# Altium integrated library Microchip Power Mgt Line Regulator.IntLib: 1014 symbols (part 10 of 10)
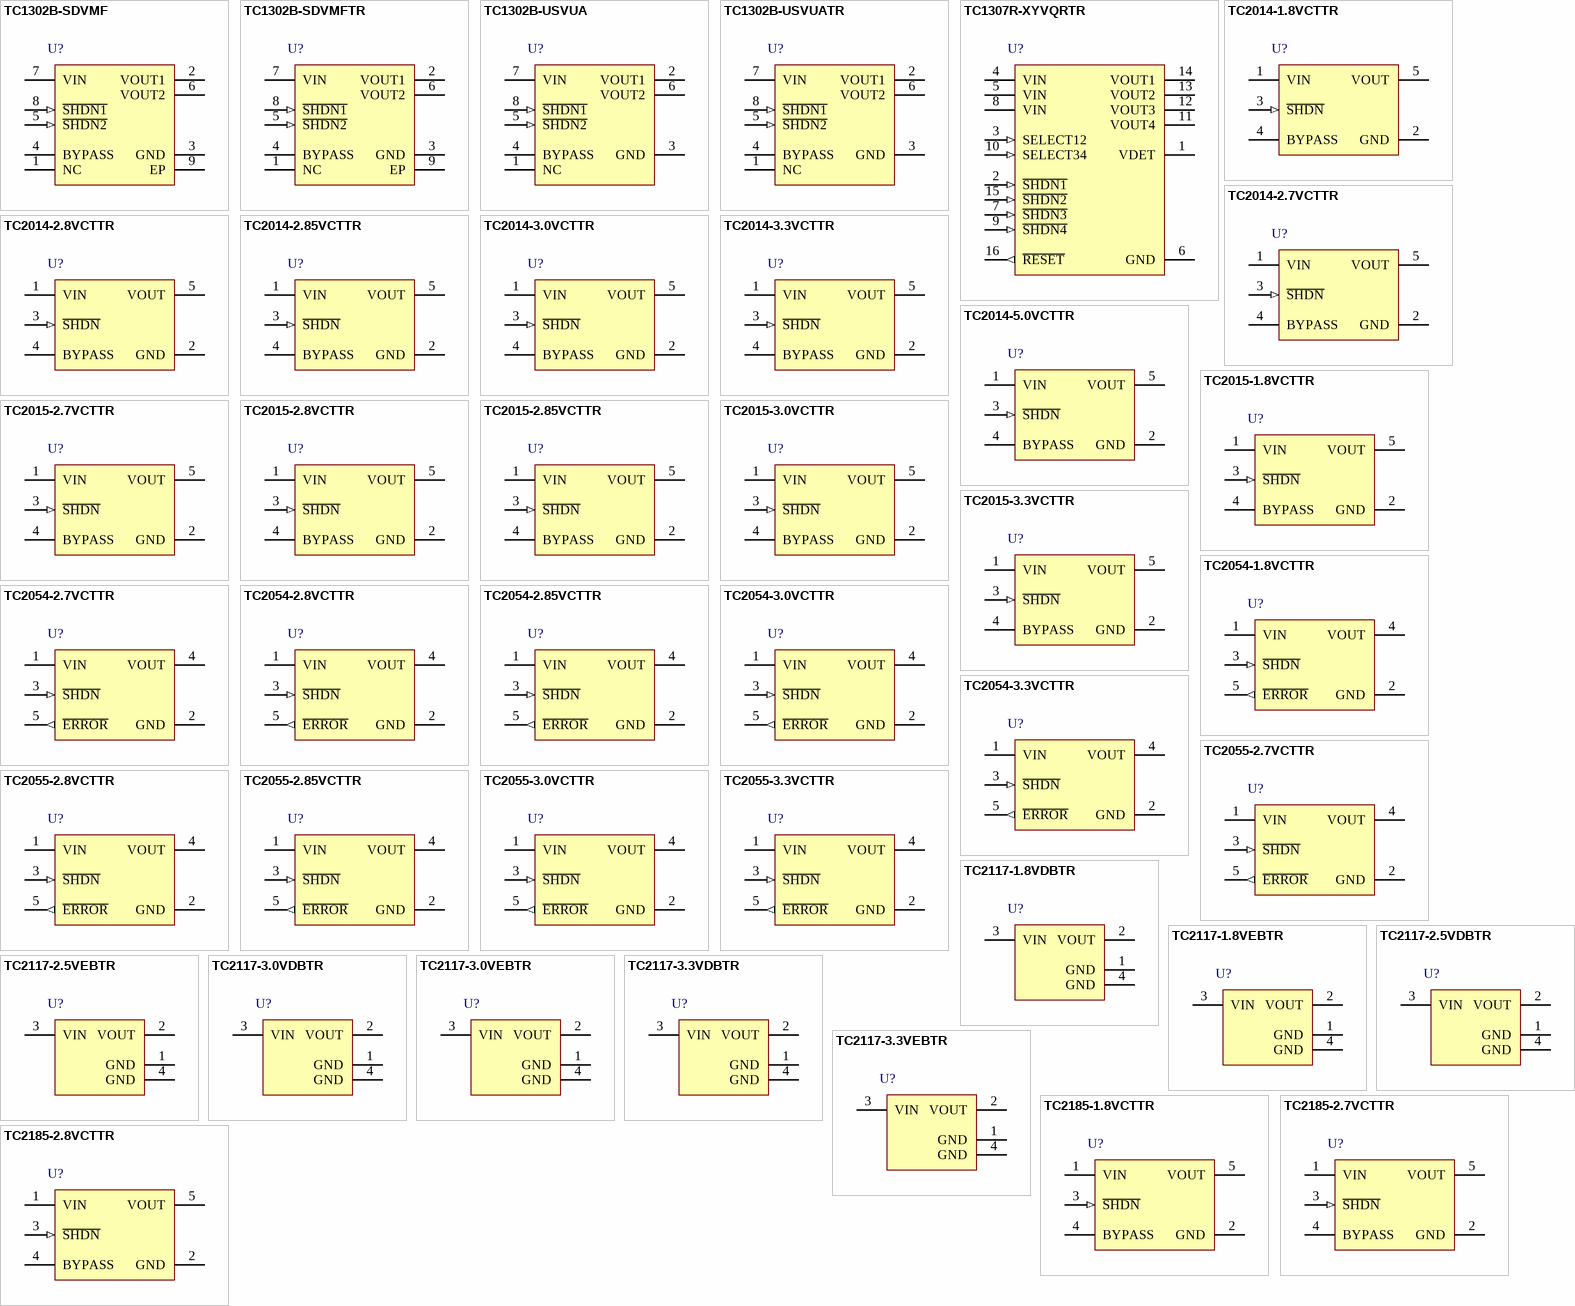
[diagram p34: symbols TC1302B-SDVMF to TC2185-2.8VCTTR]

## TC1302B-SDVMF
designator U?
Low Quiescent Current Dual Output LDO, 8-Pin DFN, Extended Temperature
footprint DFN-MF8 (SON, 8-Leads, Body 3x3mm, Pitch 0.65mm, Microchip Recommended)
pins: 1 NC, 2 VOUT1 (power), 3 GND (power), 4 BYPASS, 5 ~{SHDN2} (in), 6 VOUT2 (power), 7 VIN (power), 8 ~{SHDN1} (in), 9 EP (power)

## TC1302B-SDVMFTR
designator U?
Low Quiescent Current Dual Output LDO, 8-Pin DFN, Extended Temperature, Tape and Reel
footprint DFN-MF8 (SON, 8-Leads, Body 3x3mm, Pitch 0.65mm, Microchip Recommended)
pins: 1 NC, 2 VOUT1 (power), 3 GND (power), 4 BYPASS, 5 ~{SHDN2} (in), 6 VOUT2 (power), 7 VIN (power), 8 ~{SHDN1} (in), 9 EP (power)

## TC1302B-USVUA
designator U?
Low Quiescent Current Dual Output LDO, 8-Pin MSOP, Extended Temperature
footprint MSOP-UA8_N (TSOP, 8-Leads, Body 3x3mm, Pitch 0.65mm, IPC Medium Density)
footprint MSOP-UA8_L (TSOP, 8-Leads, Body 3x3mm, Pitch 0.65mm, IPC High Density)
footprint MSOP-UA8_M (TSOP, 8-Leads, Body 3x3mm, Pitch 0.65mm, IPC Low Density)
pins: 1 NC, 2 VOUT1 (power), 3 GND (power), 4 BYPASS, 5 ~{SHDN2} (in), 6 VOUT2 (power), 7 VIN (power), 8 ~{SHDN1} (in)

## TC1302B-USVUATR
designator U?
Low Quiescent Current Dual Output LDO, 8-Pin MSOP, Extended Temperature, Tape and Reel
footprint MSOP-UA8_N (TSOP, 8-Leads, Body 3x3mm, Pitch 0.65mm, IPC Medium Density)
footprint MSOP-UA8_L (TSOP, 8-Leads, Body 3x3mm, Pitch 0.65mm, IPC High Density)
footprint MSOP-UA8_M (TSOP, 8-Leads, Body 3x3mm, Pitch 0.65mm, IPC Low Density)
pins: 1 NC, 2 VOUT1 (power), 3 GND (power), 4 BYPASS, 5 ~{SHDN2} (in), 6 VOUT2 (power), 7 VIN (power), 8 ~{SHDN1} (in)

## TC1307R-XYVQRTR
designator U?
Four-Channel CMOS LDO with Select Mode, Shutdown and Independent Reset, 16-Pin QSOP, Extended Temperature, Tape and Reel
footprint QSOP-QR16_N (SOP, 16-Leads, Body 4.9x3.9mm, Pitch 0.635mm, IPC Medium Density)
footprint QSOP-QR16_L (SOP, 16-Leads, Body 4.9x3.9mm, Pitch 0.635mm, IPC High Density)
footprint QSOP-QR16_M (SOP, 16-Leads, Body 4.9x3.9mm, Pitch 0.635mm, IPC Low Density)
pins: 1 VDET (power), 2 ~{SHDN1} (in), 3 SELECT12 (in), 4 VIN (power), 5 VIN (power), 6 GND (power), 7 ~{SHDN3} (in), 8 VIN (power), 9 ~{SHDN4} (in), 10 SELECT34 (in), 11 VOUT4 (power), 12 VOUT3 (power), 13 VOUT2 (power), 14 VOUT1 (power), 15 ~{SHDN2} (in), 16 ~{RESET} (out)

## TC2014-1.8VCTTR
designator U?
50 mA, 100 mA, 150 mA CMOS LDOs with Shutdown and Reference Bypass, 5-Pin SOT-23, Extended Temperature, Tape and Reel
footprint SOT-23-CT5_N (SOT23, 5-Leads, Body 2.9x1.6mm, Pitch 0.95mm, Lead Span 2.7mm, IPC Medium Density)
footprint SOT-23-CT5_L (SOT23, 5-Leads, Body 2.9x1.6mm, Pitch 0.95mm, Lead Span 2.7mm, IPC High Density)
footprint SOT-23-CT5_M (SOT23, 5-Leads, Body 2.9x1.6mm, Pitch 0.95mm, Lead Span 2.7mm, IPC Low Density)
pins: 1 VIN (power), 2 GND (power), 3 ~{SHDN} (in), 4 BYPASS, 5 VOUT (power)

## TC2014-2.7VCTTR
designator U?
50 mA, 100 mA, 150 mA CMOS LDOs with Shutdown and Reference Bypass, 5-Pin SOT-23, Extended Temperature, Tape and Reel
footprint SOT-23-CT5_N (SOT23, 5-Leads, Body 2.9x1.6mm, Pitch 0.95mm, Lead Span 2.7mm, IPC Medium Density)
footprint SOT-23-CT5_L (SOT23, 5-Leads, Body 2.9x1.6mm, Pitch 0.95mm, Lead Span 2.7mm, IPC High Density)
footprint SOT-23-CT5_M (SOT23, 5-Leads, Body 2.9x1.6mm, Pitch 0.95mm, Lead Span 2.7mm, IPC Low Density)
pins: 1 VIN (power), 2 GND (power), 3 ~{SHDN} (in), 4 BYPASS, 5 VOUT (power)

## TC2014-2.8VCTTR
designator U?
50 mA, 100 mA, 150 mA CMOS LDOs with Shutdown and Reference Bypass, 5-Pin SOT-23, Extended Temperature, Tape and Reel
footprint SOT-23-CT5_N (SOT23, 5-Leads, Body 2.9x1.6mm, Pitch 0.95mm, Lead Span 2.7mm, IPC Medium Density)
footprint SOT-23-CT5_L (SOT23, 5-Leads, Body 2.9x1.6mm, Pitch 0.95mm, Lead Span 2.7mm, IPC High Density)
footprint SOT-23-CT5_M (SOT23, 5-Leads, Body 2.9x1.6mm, Pitch 0.95mm, Lead Span 2.7mm, IPC Low Density)
pins: 1 VIN (power), 2 GND (power), 3 ~{SHDN} (in), 4 BYPASS, 5 VOUT (power)

## TC2014-2.85VCTTR
designator U?
50 mA, 100 mA, 150 mA CMOS LDOs with Shutdown and Reference Bypass, 5-Pin SOT-23, Extended Temperature, Tape and Reel
footprint SOT-23-CT5_N (SOT23, 5-Leads, Body 2.9x1.6mm, Pitch 0.95mm, Lead Span 2.7mm, IPC Medium Density)
footprint SOT-23-CT5_L (SOT23, 5-Leads, Body 2.9x1.6mm, Pitch 0.95mm, Lead Span 2.7mm, IPC High Density)
footprint SOT-23-CT5_M (SOT23, 5-Leads, Body 2.9x1.6mm, Pitch 0.95mm, Lead Span 2.7mm, IPC Low Density)
pins: 1 VIN (power), 2 GND (power), 3 ~{SHDN} (in), 4 BYPASS, 5 VOUT (power)

## TC2014-3.0VCTTR
designator U?
50 mA, 100 mA, 150 mA CMOS LDOs with Shutdown and Reference Bypass, 5-Pin SOT-23, Extended Temperature, Tape and Reel
footprint SOT-23-CT5_N (SOT23, 5-Leads, Body 2.9x1.6mm, Pitch 0.95mm, Lead Span 2.7mm, IPC Medium Density)
footprint SOT-23-CT5_L (SOT23, 5-Leads, Body 2.9x1.6mm, Pitch 0.95mm, Lead Span 2.7mm, IPC High Density)
footprint SOT-23-CT5_M (SOT23, 5-Leads, Body 2.9x1.6mm, Pitch 0.95mm, Lead Span 2.7mm, IPC Low Density)
pins: 1 VIN (power), 2 GND (power), 3 ~{SHDN} (in), 4 BYPASS, 5 VOUT (power)

## TC2014-3.3VCTTR
designator U?
50 mA, 100 mA, 150 mA CMOS LDOs with Shutdown and Reference Bypass, 5-Pin SOT-23, Extended Temperature, Tape and Reel
footprint SOT-23-CT5_N (SOT23, 5-Leads, Body 2.9x1.6mm, Pitch 0.95mm, Lead Span 2.7mm, IPC Medium Density)
footprint SOT-23-CT5_L (SOT23, 5-Leads, Body 2.9x1.6mm, Pitch 0.95mm, Lead Span 2.7mm, IPC High Density)
footprint SOT-23-CT5_M (SOT23, 5-Leads, Body 2.9x1.6mm, Pitch 0.95mm, Lead Span 2.7mm, IPC Low Density)
pins: 1 VIN (power), 2 GND (power), 3 ~{SHDN} (in), 4 BYPASS, 5 VOUT (power)

## TC2014-5.0VCTTR
designator U?
50 mA, 100 mA, 150 mA CMOS LDOs with Shutdown and Reference Bypass, 5-Pin SOT-23, Extended Temperature, Tape and Reel
footprint SOT-23-CT5_N (SOT23, 5-Leads, Body 2.9x1.6mm, Pitch 0.95mm, Lead Span 2.7mm, IPC Medium Density)
footprint SOT-23-CT5_L (SOT23, 5-Leads, Body 2.9x1.6mm, Pitch 0.95mm, Lead Span 2.7mm, IPC High Density)
footprint SOT-23-CT5_M (SOT23, 5-Leads, Body 2.9x1.6mm, Pitch 0.95mm, Lead Span 2.7mm, IPC Low Density)
pins: 1 VIN (power), 2 GND (power), 3 ~{SHDN} (in), 4 BYPASS, 5 VOUT (power)

## TC2015-1.8VCTTR
designator U?
50 mA, 100 mA, 150 mA CMOS LDOs with Shutdown and Reference Bypass, 5-Pin SOT-23, Extended Temperature, Tape and Reel
footprint SOT-23-CT5_N (SOT23, 5-Leads, Body 2.9x1.6mm, Pitch 0.95mm, Lead Span 2.7mm, IPC Medium Density)
footprint SOT-23-CT5_L (SOT23, 5-Leads, Body 2.9x1.6mm, Pitch 0.95mm, Lead Span 2.7mm, IPC High Density)
footprint SOT-23-CT5_M (SOT23, 5-Leads, Body 2.9x1.6mm, Pitch 0.95mm, Lead Span 2.7mm, IPC Low Density)
pins: 1 VIN (power), 2 GND (power), 3 ~{SHDN} (in), 4 BYPASS, 5 VOUT (power)

## TC2015-2.7VCTTR
designator U?
50 mA, 100 mA, 150 mA CMOS LDOs with Shutdown and Reference Bypass, 5-Pin SOT-23, Extended Temperature, Tape and Reel
footprint SOT-23-CT5_N (SOT23, 5-Leads, Body 2.9x1.6mm, Pitch 0.95mm, Lead Span 2.7mm, IPC Medium Density)
footprint SOT-23-CT5_L (SOT23, 5-Leads, Body 2.9x1.6mm, Pitch 0.95mm, Lead Span 2.7mm, IPC High Density)
footprint SOT-23-CT5_M (SOT23, 5-Leads, Body 2.9x1.6mm, Pitch 0.95mm, Lead Span 2.7mm, IPC Low Density)
pins: 1 VIN (power), 2 GND (power), 3 ~{SHDN} (in), 4 BYPASS, 5 VOUT (power)

## TC2015-2.8VCTTR
designator U?
50 mA, 100 mA, 150 mA CMOS LDOs with Shutdown and Reference Bypass, 5-Pin SOT-23, Extended Temperature, Tape and Reel
footprint SOT-23-CT5_N (SOT23, 5-Leads, Body 2.9x1.6mm, Pitch 0.95mm, Lead Span 2.7mm, IPC Medium Density)
footprint SOT-23-CT5_L (SOT23, 5-Leads, Body 2.9x1.6mm, Pitch 0.95mm, Lead Span 2.7mm, IPC High Density)
footprint SOT-23-CT5_M (SOT23, 5-Leads, Body 2.9x1.6mm, Pitch 0.95mm, Lead Span 2.7mm, IPC Low Density)
pins: 1 VIN (power), 2 GND (power), 3 ~{SHDN} (in), 4 BYPASS, 5 VOUT (power)

## TC2015-2.85VCTTR
designator U?
50 mA, 100 mA, 150 mA CMOS LDOs with Shutdown and Reference Bypass, 5-Pin SOT-23, Extended Temperature, Tape and Reel
footprint SOT-23-CT5_N (SOT23, 5-Leads, Body 2.9x1.6mm, Pitch 0.95mm, Lead Span 2.7mm, IPC Medium Density)
footprint SOT-23-CT5_L (SOT23, 5-Leads, Body 2.9x1.6mm, Pitch 0.95mm, Lead Span 2.7mm, IPC High Density)
footprint SOT-23-CT5_M (SOT23, 5-Leads, Body 2.9x1.6mm, Pitch 0.95mm, Lead Span 2.7mm, IPC Low Density)
pins: 1 VIN (power), 2 GND (power), 3 ~{SHDN} (in), 4 BYPASS, 5 VOUT (power)

## TC2015-3.0VCTTR
designator U?
50 mA, 100 mA, 150 mA CMOS LDOs with Shutdown and Reference Bypass, 5-Pin SOT-23, Extended Temperature, Tape and Reel
footprint SOT-23-CT5_N (SOT23, 5-Leads, Body 2.9x1.6mm, Pitch 0.95mm, Lead Span 2.7mm, IPC Medium Density)
footprint SOT-23-CT5_L (SOT23, 5-Leads, Body 2.9x1.6mm, Pitch 0.95mm, Lead Span 2.7mm, IPC High Density)
footprint SOT-23-CT5_M (SOT23, 5-Leads, Body 2.9x1.6mm, Pitch 0.95mm, Lead Span 2.7mm, IPC Low Density)
pins: 1 VIN (power), 2 GND (power), 3 ~{SHDN} (in), 4 BYPASS, 5 VOUT (power)

## TC2015-3.3VCTTR
designator U?
50 mA, 100 mA, 150 mA CMOS LDOs with Shutdown and Reference Bypass, 5-Pin SOT-23, Extended Temperature, Tape and Reel
footprint SOT-23-CT5_N (SOT23, 5-Leads, Body 2.9x1.6mm, Pitch 0.95mm, Lead Span 2.7mm, IPC Medium Density)
footprint SOT-23-CT5_L (SOT23, 5-Leads, Body 2.9x1.6mm, Pitch 0.95mm, Lead Span 2.7mm, IPC High Density)
footprint SOT-23-CT5_M (SOT23, 5-Leads, Body 2.9x1.6mm, Pitch 0.95mm, Lead Span 2.7mm, IPC Low Density)
pins: 1 VIN (power), 2 GND (power), 3 ~{SHDN} (in), 4 BYPASS, 5 VOUT (power)

## TC2054-1.8VCTTR
designator U?
50 mA, 100 mA, and 150 mA CMOS LDOs with Shutdown and Active-Low Error Output, 5-Pin SOT-23, Extended Temperature, Tape and Reel
footprint SOT-23-CT5_N (SOT23, 5-Leads, Body 2.9x1.6mm, Pitch 0.95mm, Lead Span 2.7mm, IPC Medium Density)
footprint SOT-23-CT5_L (SOT23, 5-Leads, Body 2.9x1.6mm, Pitch 0.95mm, Lead Span 2.7mm, IPC High Density)
footprint SOT-23-CT5_M (SOT23, 5-Leads, Body 2.9x1.6mm, Pitch 0.95mm, Lead Span 2.7mm, IPC Low Density)
pins: 1 VIN (power), 2 GND (power), 3 ~{SHDN} (in), 4 VOUT (power), 5 ~{ERROR} (out)

## TC2054-2.7VCTTR
designator U?
50 mA, 100 mA, and 150 mA CMOS LDOs with Shutdown and Active-Low Error Output, 5-Pin SOT-23, Extended Temperature, Tape and Reel
footprint SOT-23-CT5_N (SOT23, 5-Leads, Body 2.9x1.6mm, Pitch 0.95mm, Lead Span 2.7mm, IPC Medium Density)
footprint SOT-23-CT5_L (SOT23, 5-Leads, Body 2.9x1.6mm, Pitch 0.95mm, Lead Span 2.7mm, IPC High Density)
footprint SOT-23-CT5_M (SOT23, 5-Leads, Body 2.9x1.6mm, Pitch 0.95mm, Lead Span 2.7mm, IPC Low Density)
pins: 1 VIN (power), 2 GND (power), 3 ~{SHDN} (in), 4 VOUT (power), 5 ~{ERROR} (out)

## TC2054-2.8VCTTR
designator U?
50 mA, 100 mA, and 150 mA CMOS LDOs with Shutdown and Active-Low Error Output, 5-Pin SOT-23, Extended Temperature, Tape and Reel
footprint SOT-23-CT5_N (SOT23, 5-Leads, Body 2.9x1.6mm, Pitch 0.95mm, Lead Span 2.7mm, IPC Medium Density)
footprint SOT-23-CT5_L (SOT23, 5-Leads, Body 2.9x1.6mm, Pitch 0.95mm, Lead Span 2.7mm, IPC High Density)
footprint SOT-23-CT5_M (SOT23, 5-Leads, Body 2.9x1.6mm, Pitch 0.95mm, Lead Span 2.7mm, IPC Low Density)
pins: 1 VIN (power), 2 GND (power), 3 ~{SHDN} (in), 4 VOUT (power), 5 ~{ERROR} (out)

## TC2054-2.85VCTTR
designator U?
50 mA, 100 mA, and 150 mA CMOS LDOs with Shutdown and Active-Low Error Output, 5-Pin SOT-23, Extended Temperature, Tape and Reel
footprint SOT-23-CT5_N (SOT23, 5-Leads, Body 2.9x1.6mm, Pitch 0.95mm, Lead Span 2.7mm, IPC Medium Density)
footprint SOT-23-CT5_L (SOT23, 5-Leads, Body 2.9x1.6mm, Pitch 0.95mm, Lead Span 2.7mm, IPC High Density)
footprint SOT-23-CT5_M (SOT23, 5-Leads, Body 2.9x1.6mm, Pitch 0.95mm, Lead Span 2.7mm, IPC Low Density)
pins: 1 VIN (power), 2 GND (power), 3 ~{SHDN} (in), 4 VOUT (power), 5 ~{ERROR} (out)

## TC2054-3.0VCTTR
designator U?
50 mA, 100 mA, and 150 mA CMOS LDOs with Shutdown and Active-Low Error Output, 5-Pin SOT-23, Extended Temperature, Tape and Reel
footprint SOT-23-CT5_N (SOT23, 5-Leads, Body 2.9x1.6mm, Pitch 0.95mm, Lead Span 2.7mm, IPC Medium Density)
footprint SOT-23-CT5_L (SOT23, 5-Leads, Body 2.9x1.6mm, Pitch 0.95mm, Lead Span 2.7mm, IPC High Density)
footprint SOT-23-CT5_M (SOT23, 5-Leads, Body 2.9x1.6mm, Pitch 0.95mm, Lead Span 2.7mm, IPC Low Density)
pins: 1 VIN (power), 2 GND (power), 3 ~{SHDN} (in), 4 VOUT (power), 5 ~{ERROR} (out)

## TC2054-3.3VCTTR
designator U?
50 mA, 100 mA, and 150 mA CMOS LDOs with Shutdown and Active-Low Error Output, 5-Pin SOT-23, Extended Temperature, Tape and Reel
footprint SOT-23-CT5_N (SOT23, 5-Leads, Body 2.9x1.6mm, Pitch 0.95mm, Lead Span 2.7mm, IPC Medium Density)
footprint SOT-23-CT5_L (SOT23, 5-Leads, Body 2.9x1.6mm, Pitch 0.95mm, Lead Span 2.7mm, IPC High Density)
footprint SOT-23-CT5_M (SOT23, 5-Leads, Body 2.9x1.6mm, Pitch 0.95mm, Lead Span 2.7mm, IPC Low Density)
pins: 1 VIN (power), 2 GND (power), 3 ~{SHDN} (in), 4 VOUT (power), 5 ~{ERROR} (out)

## TC2055-2.7VCTTR
designator U?
50 mA, 100 mA, and 150 mA CMOS LDOs with Shutdown and Active-Low Error Output, 5-Pin SOT-23, Extended Temperature, Tape and Reel
footprint SOT-23-CT5_N (SOT23, 5-Leads, Body 2.9x1.6mm, Pitch 0.95mm, Lead Span 2.7mm, IPC Medium Density)
footprint SOT-23-CT5_L (SOT23, 5-Leads, Body 2.9x1.6mm, Pitch 0.95mm, Lead Span 2.7mm, IPC High Density)
footprint SOT-23-CT5_M (SOT23, 5-Leads, Body 2.9x1.6mm, Pitch 0.95mm, Lead Span 2.7mm, IPC Low Density)
pins: 1 VIN (power), 2 GND (power), 3 ~{SHDN} (in), 4 VOUT (power), 5 ~{ERROR} (out)

## TC2055-2.8VCTTR
designator U?
50 mA, 100 mA, and 150 mA CMOS LDOs with Shutdown and Active-Low Error Output, 5-Pin SOT-23, Extended Temperature, Tape and Reel
footprint SOT-23-CT5_N (SOT23, 5-Leads, Body 2.9x1.6mm, Pitch 0.95mm, Lead Span 2.7mm, IPC Medium Density)
footprint SOT-23-CT5_L (SOT23, 5-Leads, Body 2.9x1.6mm, Pitch 0.95mm, Lead Span 2.7mm, IPC High Density)
footprint SOT-23-CT5_M (SOT23, 5-Leads, Body 2.9x1.6mm, Pitch 0.95mm, Lead Span 2.7mm, IPC Low Density)
pins: 1 VIN (power), 2 GND (power), 3 ~{SHDN} (in), 4 VOUT (power), 5 ~{ERROR} (out)

## TC2055-2.85VCTTR
designator U?
50 mA, 100 mA, and 150 mA CMOS LDOs with Shutdown and Active-Low Error Output, 5-Pin SOT-23, Extended Temperature, Tape and Reel
footprint SOT-23-CT5_N (SOT23, 5-Leads, Body 2.9x1.6mm, Pitch 0.95mm, Lead Span 2.7mm, IPC Medium Density)
footprint SOT-23-CT5_L (SOT23, 5-Leads, Body 2.9x1.6mm, Pitch 0.95mm, Lead Span 2.7mm, IPC High Density)
footprint SOT-23-CT5_M (SOT23, 5-Leads, Body 2.9x1.6mm, Pitch 0.95mm, Lead Span 2.7mm, IPC Low Density)
pins: 1 VIN (power), 2 GND (power), 3 ~{SHDN} (in), 4 VOUT (power), 5 ~{ERROR} (out)

## TC2055-3.0VCTTR
designator U?
50 mA, 100 mA, and 150 mA CMOS LDOs with Shutdown and Active-Low Error Output, 5-Pin SOT-23, Extended Temperature, Tape and Reel
footprint SOT-23-CT5_N (SOT23, 5-Leads, Body 2.9x1.6mm, Pitch 0.95mm, Lead Span 2.7mm, IPC Medium Density)
footprint SOT-23-CT5_L (SOT23, 5-Leads, Body 2.9x1.6mm, Pitch 0.95mm, Lead Span 2.7mm, IPC High Density)
footprint SOT-23-CT5_M (SOT23, 5-Leads, Body 2.9x1.6mm, Pitch 0.95mm, Lead Span 2.7mm, IPC Low Density)
pins: 1 VIN (power), 2 GND (power), 3 ~{SHDN} (in), 4 VOUT (power), 5 ~{ERROR} (out)

## TC2055-3.3VCTTR
designator U?
50 mA, 100 mA, and 150 mA CMOS LDOs with Shutdown and Active-Low Error Output, 5-Pin SOT-23, Extended Temperature, Tape and Reel
footprint SOT-23-CT5_N (SOT23, 5-Leads, Body 2.9x1.6mm, Pitch 0.95mm, Lead Span 2.7mm, IPC Medium Density)
footprint SOT-23-CT5_L (SOT23, 5-Leads, Body 2.9x1.6mm, Pitch 0.95mm, Lead Span 2.7mm, IPC High Density)
footprint SOT-23-CT5_M (SOT23, 5-Leads, Body 2.9x1.6mm, Pitch 0.95mm, Lead Span 2.7mm, IPC Low Density)
pins: 1 VIN (power), 2 GND (power), 3 ~{SHDN} (in), 4 VOUT (power), 5 ~{ERROR} (out)

## TC2117-1.8VDBTR
designator U?
800 mA Fixed Low Dropout Positive Regulator, 3-Pin SOT-223, Extended Temperature, Tape and Reel
footprint SOT-223-DB3_N (SOT223, 4-Leads, Body 6.5x3.5mm, Pitch 2.3mm, Lead Span 7mm, IPC Medium Density)
footprint SOT-223-DB3_L (SOT223, 4-Leads, Body 6.5x3.5mm, Pitch 2.3mm, Lead Span 7mm, IPC High Density)
footprint SOT-223-DB3_M (SOT223, 4-Leads, Body 6.5x3.5mm, Pitch 2.3mm, Lead Span 7mm, IPC Low Density)
pins: 1 GND (power), 2 VOUT (power), 3 VIN (power), 4 GND (power)

## TC2117-1.8VEBTR
designator U?
800 mA Fixed Low Dropout Positive Regulator, 3-Pin DDPAK, Extended Temperature, Tape and Reel
footprint DDPAK-EB3_N (D2-PAK, 4-Leads, Body 9x10.2mm, Pitch 2.54mm, Lead Span 14.9mm, IPC Medium Density)
footprint DDPAK-EB3_L (D2-PAK, 4-Leads, Body 9x10.2mm, Pitch 2.54mm, Lead Span 14.9mm, IPC High Density)
footprint DDPAK-EB3_M (D2-PAK, 4-Leads, Body 9x10.2mm, Pitch 2.54mm, Lead Span 14.9mm, IPC Low Density)
pins: 1 GND (power), 2 VOUT (power), 3 VIN (power), 4 GND (power)

## TC2117-2.5VDBTR
designator U?
800 mA Fixed Low Dropout Positive Regulator, 3-Pin SOT-223, Extended Temperature, Tape and Reel
footprint SOT-223-DB3_N (SOT223, 4-Leads, Body 6.5x3.5mm, Pitch 2.3mm, Lead Span 7mm, IPC Medium Density)
footprint SOT-223-DB3_L (SOT223, 4-Leads, Body 6.5x3.5mm, Pitch 2.3mm, Lead Span 7mm, IPC High Density)
footprint SOT-223-DB3_M (SOT223, 4-Leads, Body 6.5x3.5mm, Pitch 2.3mm, Lead Span 7mm, IPC Low Density)
pins: 1 GND (power), 2 VOUT (power), 3 VIN (power), 4 GND (power)

## TC2117-2.5VEBTR
designator U?
800 mA Fixed Low Dropout Positive Regulator, 3-Pin DDPAK, Extended Temperature, Tape and Reel
footprint DDPAK-EB3_N (D2-PAK, 4-Leads, Body 9x10.2mm, Pitch 2.54mm, Lead Span 14.9mm, IPC Medium Density)
footprint DDPAK-EB3_L (D2-PAK, 4-Leads, Body 9x10.2mm, Pitch 2.54mm, Lead Span 14.9mm, IPC High Density)
footprint DDPAK-EB3_M (D2-PAK, 4-Leads, Body 9x10.2mm, Pitch 2.54mm, Lead Span 14.9mm, IPC Low Density)
pins: 1 GND (power), 2 VOUT (power), 3 VIN (power), 4 GND (power)

## TC2117-3.0VDBTR
designator U?
800 mA Fixed Low Dropout Positive Regulator, 3-Pin SOT-223, Extended Temperature, Tape and Reel
footprint SOT-223-DB3_N (SOT223, 4-Leads, Body 6.5x3.5mm, Pitch 2.3mm, Lead Span 7mm, IPC Medium Density)
footprint SOT-223-DB3_L (SOT223, 4-Leads, Body 6.5x3.5mm, Pitch 2.3mm, Lead Span 7mm, IPC High Density)
footprint SOT-223-DB3_M (SOT223, 4-Leads, Body 6.5x3.5mm, Pitch 2.3mm, Lead Span 7mm, IPC Low Density)
pins: 1 GND (power), 2 VOUT (power), 3 VIN (power), 4 GND (power)

## TC2117-3.0VEBTR
designator U?
800 mA Fixed Low Dropout Positive Regulator, 3-Pin DDPAK, Extended Temperature, Tape and Reel
footprint DDPAK-EB3_N (D2-PAK, 4-Leads, Body 9x10.2mm, Pitch 2.54mm, Lead Span 14.9mm, IPC Medium Density)
footprint DDPAK-EB3_L (D2-PAK, 4-Leads, Body 9x10.2mm, Pitch 2.54mm, Lead Span 14.9mm, IPC High Density)
footprint DDPAK-EB3_M (D2-PAK, 4-Leads, Body 9x10.2mm, Pitch 2.54mm, Lead Span 14.9mm, IPC Low Density)
pins: 1 GND (power), 2 VOUT (power), 3 VIN (power), 4 GND (power)

## TC2117-3.3VDBTR
designator U?
800 mA Fixed Low Dropout Positive Regulator, 3-Pin SOT-223, Extended Temperature, Tape and Reel
footprint SOT-223-DB3_N (SOT223, 4-Leads, Body 6.5x3.5mm, Pitch 2.3mm, Lead Span 7mm, IPC Medium Density)
footprint SOT-223-DB3_L (SOT223, 4-Leads, Body 6.5x3.5mm, Pitch 2.3mm, Lead Span 7mm, IPC High Density)
footprint SOT-223-DB3_M (SOT223, 4-Leads, Body 6.5x3.5mm, Pitch 2.3mm, Lead Span 7mm, IPC Low Density)
pins: 1 GND (power), 2 VOUT (power), 3 VIN (power), 4 GND (power)

## TC2117-3.3VEBTR
designator U?
800 mA Fixed Low Dropout Positive Regulator, 3-Pin DDPAK, Extended Temperature, Tape and Reel
footprint DDPAK-EB3_N (D2-PAK, 4-Leads, Body 9x10.2mm, Pitch 2.54mm, Lead Span 14.9mm, IPC Medium Density)
footprint DDPAK-EB3_L (D2-PAK, 4-Leads, Body 9x10.2mm, Pitch 2.54mm, Lead Span 14.9mm, IPC High Density)
footprint DDPAK-EB3_M (D2-PAK, 4-Leads, Body 9x10.2mm, Pitch 2.54mm, Lead Span 14.9mm, IPC Low Density)
pins: 1 GND (power), 2 VOUT (power), 3 VIN (power), 4 GND (power)

## TC2185-1.8VCTTR
designator U?
50 mA, 100 mA, 150 mA CMOS LDOs with Shutdown and Reference Bypass, 5-Pin SOT-23, Extended Temperature, Tape and Reel
footprint SOT-23-CT5_N (SOT23, 5-Leads, Body 2.9x1.6mm, Pitch 0.95mm, Lead Span 2.7mm, IPC Medium Density)
footprint SOT-23-CT5_L (SOT23, 5-Leads, Body 2.9x1.6mm, Pitch 0.95mm, Lead Span 2.7mm, IPC High Density)
footprint SOT-23-CT5_M (SOT23, 5-Leads, Body 2.9x1.6mm, Pitch 0.95mm, Lead Span 2.7mm, IPC Low Density)
pins: 1 VIN (power), 2 GND (power), 3 ~{SHDN} (in), 4 BYPASS, 5 VOUT (power)

## TC2185-2.7VCTTR
designator U?
50 mA, 100 mA, 150 mA CMOS LDOs with Shutdown and Reference Bypass, 5-Pin SOT-23, Extended Temperature, Tape and Reel
footprint SOT-23-CT5_N (SOT23, 5-Leads, Body 2.9x1.6mm, Pitch 0.95mm, Lead Span 2.7mm, IPC Medium Density)
footprint SOT-23-CT5_L (SOT23, 5-Leads, Body 2.9x1.6mm, Pitch 0.95mm, Lead Span 2.7mm, IPC High Density)
footprint SOT-23-CT5_M (SOT23, 5-Leads, Body 2.9x1.6mm, Pitch 0.95mm, Lead Span 2.7mm, IPC Low Density)
pins: 1 VIN (power), 2 GND (power), 3 ~{SHDN} (in), 4 BYPASS, 5 VOUT (power)

## TC2185-2.8VCTTR
designator U?
50 mA, 100 mA, 150 mA CMOS LDOs with Shutdown and Reference Bypass, 5-Pin SOT-23, Extended Temperature, Tape and Reel
footprint SOT-23-CT5_N (SOT23, 5-Leads, Body 2.9x1.6mm, Pitch 0.95mm, Lead Span 2.7mm, IPC Medium Density)
footprint SOT-23-CT5_L (SOT23, 5-Leads, Body 2.9x1.6mm, Pitch 0.95mm, Lead Span 2.7mm, IPC High Density)
footprint SOT-23-CT5_M (SOT23, 5-Leads, Body 2.9x1.6mm, Pitch 0.95mm, Lead Span 2.7mm, IPC Low Density)
pins: 1 VIN (power), 2 GND (power), 3 ~{SHDN} (in), 4 BYPASS, 5 VOUT (power)

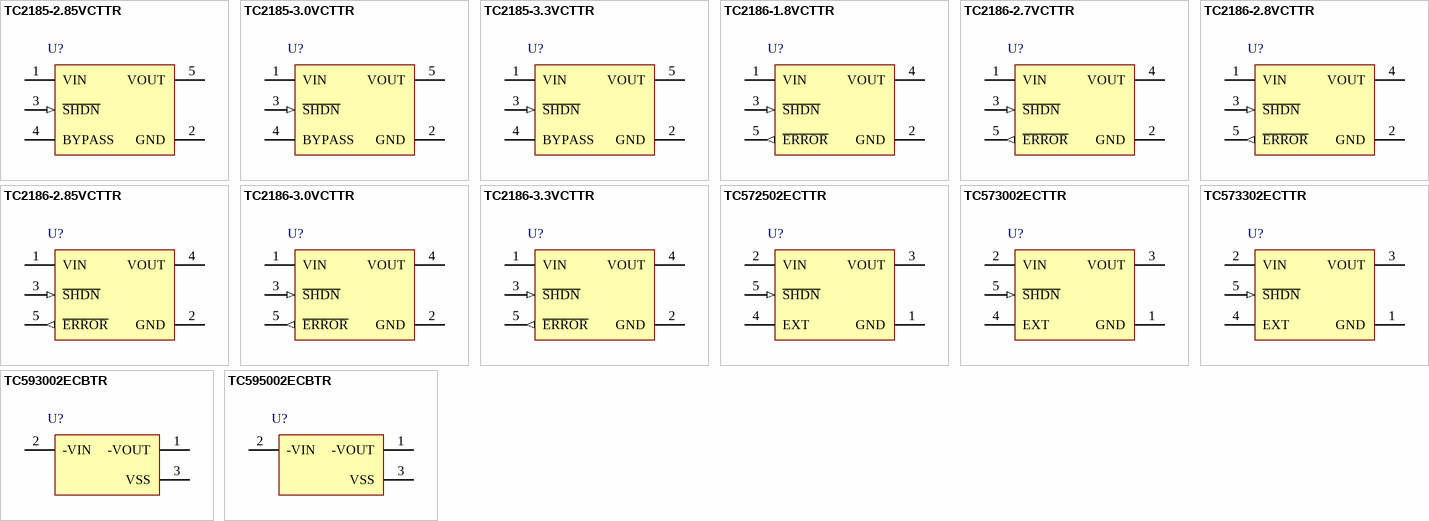
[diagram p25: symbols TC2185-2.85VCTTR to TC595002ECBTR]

## TC2185-2.85VCTTR
designator U?
50 mA, 100 mA, 150 mA CMOS LDOs with Shutdown and Reference Bypass, 5-Pin SOT-23, Extended Temperature, Tape and Reel
footprint SOT-23-CT5_N (SOT23, 5-Leads, Body 2.9x1.6mm, Pitch 0.95mm, Lead Span 2.7mm, IPC Medium Density)
footprint SOT-23-CT5_L (SOT23, 5-Leads, Body 2.9x1.6mm, Pitch 0.95mm, Lead Span 2.7mm, IPC High Density)
footprint SOT-23-CT5_M (SOT23, 5-Leads, Body 2.9x1.6mm, Pitch 0.95mm, Lead Span 2.7mm, IPC Low Density)
pins: 1 VIN (power), 2 GND (power), 3 ~{SHDN} (in), 4 BYPASS, 5 VOUT (power)

## TC2185-3.0VCTTR
designator U?
50 mA, 100 mA, 150 mA CMOS LDOs with Shutdown and Reference Bypass, 5-Pin SOT-23, Extended Temperature, Tape and Reel
footprint SOT-23-CT5_N (SOT23, 5-Leads, Body 2.9x1.6mm, Pitch 0.95mm, Lead Span 2.7mm, IPC Medium Density)
footprint SOT-23-CT5_L (SOT23, 5-Leads, Body 2.9x1.6mm, Pitch 0.95mm, Lead Span 2.7mm, IPC High Density)
footprint SOT-23-CT5_M (SOT23, 5-Leads, Body 2.9x1.6mm, Pitch 0.95mm, Lead Span 2.7mm, IPC Low Density)
pins: 1 VIN (power), 2 GND (power), 3 ~{SHDN} (in), 4 BYPASS, 5 VOUT (power)

## TC2185-3.3VCTTR
designator U?
50 mA, 100 mA, 150 mA CMOS LDOs with Shutdown and Reference Bypass, 5-Pin SOT-23, Extended Temperature, Tape and Reel
footprint SOT-23-CT5_N (SOT23, 5-Leads, Body 2.9x1.6mm, Pitch 0.95mm, Lead Span 2.7mm, IPC Medium Density)
footprint SOT-23-CT5_L (SOT23, 5-Leads, Body 2.9x1.6mm, Pitch 0.95mm, Lead Span 2.7mm, IPC High Density)
footprint SOT-23-CT5_M (SOT23, 5-Leads, Body 2.9x1.6mm, Pitch 0.95mm, Lead Span 2.7mm, IPC Low Density)
pins: 1 VIN (power), 2 GND (power), 3 ~{SHDN} (in), 4 BYPASS, 5 VOUT (power)

## TC2186-1.8VCTTR
designator U?
50 mA, 100 mA, 150 mA CMOS LDOs with Shutdown and Reference Bypass, 5-Pin SOT-23, Extended Temperature, Tape and Reel
footprint SOT-23-CT5_N (SOT23, 5-Leads, Body 2.9x1.6mm, Pitch 0.95mm, Lead Span 2.7mm, IPC Medium Density)
footprint SOT-23-CT5_L (SOT23, 5-Leads, Body 2.9x1.6mm, Pitch 0.95mm, Lead Span 2.7mm, IPC High Density)
footprint SOT-23-CT5_M (SOT23, 5-Leads, Body 2.9x1.6mm, Pitch 0.95mm, Lead Span 2.7mm, IPC Low Density)
pins: 1 VIN (power), 2 GND (power), 3 ~{SHDN} (in), 4 VOUT (power), 5 ~{ERROR} (out)

## TC2186-2.7VCTTR
designator U?
50 mA, 100 mA, 150 mA CMOS LDOs with Shutdown and Reference Bypass, 5-Pin SOT-23, Extended Temperature, Tape and Reel
footprint SOT-23-CT5_N (SOT23, 5-Leads, Body 2.9x1.6mm, Pitch 0.95mm, Lead Span 2.7mm, IPC Medium Density)
footprint SOT-23-CT5_L (SOT23, 5-Leads, Body 2.9x1.6mm, Pitch 0.95mm, Lead Span 2.7mm, IPC High Density)
footprint SOT-23-CT5_M (SOT23, 5-Leads, Body 2.9x1.6mm, Pitch 0.95mm, Lead Span 2.7mm, IPC Low Density)
pins: 1 VIN (power), 2 GND (power), 3 ~{SHDN} (in), 4 VOUT (power), 5 ~{ERROR} (out)

## TC2186-2.8VCTTR
designator U?
50 mA, 100 mA, 150 mA CMOS LDOs with Shutdown and Reference Bypass, 5-Pin SOT-23, Extended Temperature, Tape and Reel
footprint SOT-23-CT5_N (SOT23, 5-Leads, Body 2.9x1.6mm, Pitch 0.95mm, Lead Span 2.7mm, IPC Medium Density)
footprint SOT-23-CT5_L (SOT23, 5-Leads, Body 2.9x1.6mm, Pitch 0.95mm, Lead Span 2.7mm, IPC High Density)
footprint SOT-23-CT5_M (SOT23, 5-Leads, Body 2.9x1.6mm, Pitch 0.95mm, Lead Span 2.7mm, IPC Low Density)
pins: 1 VIN (power), 2 GND (power), 3 ~{SHDN} (in), 4 VOUT (power), 5 ~{ERROR} (out)

## TC2186-2.85VCTTR
designator U?
50 mA, 100 mA, 150 mA CMOS LDOs with Shutdown and Reference Bypass, 5-Pin SOT-23, Extended Temperature, Tape and Reel
footprint SOT-23-CT5_N (SOT23, 5-Leads, Body 2.9x1.6mm, Pitch 0.95mm, Lead Span 2.7mm, IPC Medium Density)
footprint SOT-23-CT5_L (SOT23, 5-Leads, Body 2.9x1.6mm, Pitch 0.95mm, Lead Span 2.7mm, IPC High Density)
footprint SOT-23-CT5_M (SOT23, 5-Leads, Body 2.9x1.6mm, Pitch 0.95mm, Lead Span 2.7mm, IPC Low Density)
pins: 1 VIN (power), 2 GND (power), 3 ~{SHDN} (in), 4 VOUT (power), 5 ~{ERROR} (out)

## TC2186-3.0VCTTR
designator U?
50 mA, 100 mA, 150 mA CMOS LDOs with Shutdown and Reference Bypass, 5-Pin SOT-23, Extended Temperature, Tape and Reel
footprint SOT-23-CT5_N (SOT23, 5-Leads, Body 2.9x1.6mm, Pitch 0.95mm, Lead Span 2.7mm, IPC Medium Density)
footprint SOT-23-CT5_L (SOT23, 5-Leads, Body 2.9x1.6mm, Pitch 0.95mm, Lead Span 2.7mm, IPC High Density)
footprint SOT-23-CT5_M (SOT23, 5-Leads, Body 2.9x1.6mm, Pitch 0.95mm, Lead Span 2.7mm, IPC Low Density)
pins: 1 VIN (power), 2 GND (power), 3 ~{SHDN} (in), 4 VOUT (power), 5 ~{ERROR} (out)

## TC2186-3.3VCTTR
designator U?
50 mA, 100 mA, 150 mA CMOS LDOs with Shutdown and Reference Bypass, 5-Pin SOT-23, Extended Temperature, Tape and Reel
footprint SOT-23-CT5_N (SOT23, 5-Leads, Body 2.9x1.6mm, Pitch 0.95mm, Lead Span 2.7mm, IPC Medium Density)
footprint SOT-23-CT5_L (SOT23, 5-Leads, Body 2.9x1.6mm, Pitch 0.95mm, Lead Span 2.7mm, IPC High Density)
footprint SOT-23-CT5_M (SOT23, 5-Leads, Body 2.9x1.6mm, Pitch 0.95mm, Lead Span 2.7mm, IPC Low Density)
pins: 1 VIN (power), 2 GND (power), 3 ~{SHDN} (in), 4 VOUT (power), 5 ~{ERROR} (out)

## TC572502ECTTR
designator U?
Line Regulator Controller, 5-Pin SOT-23, Industrial Temperature, Tape and Reel
footprint SOT-23-CT5_N (SOT23, 5-Leads, Body 2.9x1.6mm, Pitch 0.95mm, Lead Span 2.7mm, IPC Medium Density)
footprint SOT-23-CT5_L (SOT23, 5-Leads, Body 2.9x1.6mm, Pitch 0.95mm, Lead Span 2.7mm, IPC High Density)
footprint SOT-23-CT5_M (SOT23, 5-Leads, Body 2.9x1.6mm, Pitch 0.95mm, Lead Span 2.7mm, IPC Low Density)
pins: 1 GND (power), 2 VIN (power), 3 VOUT (power), 4 EXT, 5 ~{SHDN} (in)

## TC573002ECTTR
designator U?
Line Regulator Controller, 5-Pin SOT-23, Industrial Temperature, Tape and Reel
footprint SOT-23-CT5_N (SOT23, 5-Leads, Body 2.9x1.6mm, Pitch 0.95mm, Lead Span 2.7mm, IPC Medium Density)
footprint SOT-23-CT5_L (SOT23, 5-Leads, Body 2.9x1.6mm, Pitch 0.95mm, Lead Span 2.7mm, IPC High Density)
footprint SOT-23-CT5_M (SOT23, 5-Leads, Body 2.9x1.6mm, Pitch 0.95mm, Lead Span 2.7mm, IPC Low Density)
pins: 1 GND (power), 2 VIN (power), 3 VOUT (power), 4 EXT, 5 ~{SHDN} (in)

## TC573302ECTTR
designator U?
Line Regulator Controller, 5-Pin SOT-23, Industrial Temperature, Tape and Reel
footprint SOT-23-CT5_N (SOT23, 5-Leads, Body 2.9x1.6mm, Pitch 0.95mm, Lead Span 2.7mm, IPC Medium Density)
footprint SOT-23-CT5_L (SOT23, 5-Leads, Body 2.9x1.6mm, Pitch 0.95mm, Lead Span 2.7mm, IPC High Density)
footprint SOT-23-CT5_M (SOT23, 5-Leads, Body 2.9x1.6mm, Pitch 0.95mm, Lead Span 2.7mm, IPC Low Density)
pins: 1 GND (power), 2 VIN (power), 3 VOUT (power), 4 EXT, 5 ~{SHDN} (in)

## TC593002ECBTR
designator U?
Low Dropout, Negative Output Voltage Regulator, 3-Pin SOT-23A, Industrial Temperature, Tape and Reel
footprint SOT-23A-CB3_N (SOT346, 3-Leads, Body 2.9x1.5mm, Pitch 0.95mm, Lead Span 2.6mm, IPC Medium Density)
footprint SOT-23A-CB3_L (SOT346, 3-Leads, Body 2.9x1.5mm, Pitch 0.95mm, Lead Span 2.6mm, IPC High Density)
footprint SOT-23A-CB3_M (SOT346, 3-Leads, Body 2.9x1.5mm, Pitch 0.95mm, Lead Span 2.6mm, IPC Low Density)
pins: 1 -VOUT (power), 2 -VIN (power), 3 VSS (power)

## TC595002ECBTR
designator U?
Low Dropout, Negative Output Voltage Regulator, 3-Pin SOT-23A, Industrial Temperature, Tape and Reel
footprint SOT-23A-CB3_N (SOT346, 3-Leads, Body 2.9x1.5mm, Pitch 0.95mm, Lead Span 2.6mm, IPC Medium Density)
footprint SOT-23A-CB3_L (SOT346, 3-Leads, Body 2.9x1.5mm, Pitch 0.95mm, Lead Span 2.6mm, IPC High Density)
footprint SOT-23A-CB3_M (SOT346, 3-Leads, Body 2.9x1.5mm, Pitch 0.95mm, Lead Span 2.6mm, IPC Low Density)
pins: 1 -VOUT (power), 2 -VIN (power), 3 VSS (power)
